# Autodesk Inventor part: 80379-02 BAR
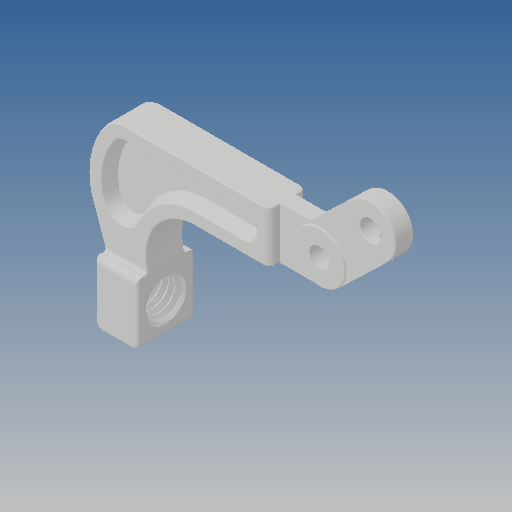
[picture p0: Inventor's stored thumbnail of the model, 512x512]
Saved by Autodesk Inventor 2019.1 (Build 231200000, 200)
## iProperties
Created: 2012-10
Part Number: 80379-02 BAR
Material: Ogólny
Document SubType Name: Modeling
Designer: CADENGINEERING4
Density: 1 g/cm^3
Appearance: Domyślna
Author: CADENGINEERING4
Revision Number: ÈÎºÎ
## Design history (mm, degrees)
feature "ÇÐ³ý-É¨Ãè2"
node "Bryła1"
